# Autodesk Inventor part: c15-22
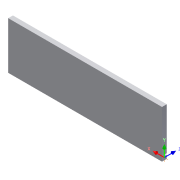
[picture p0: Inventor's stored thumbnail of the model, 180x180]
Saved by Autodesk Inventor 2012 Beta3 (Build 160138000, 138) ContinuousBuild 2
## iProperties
Created: 2011-02
Part Number: c15-22
Material: Default
Document SubType Name: Modeling
Designer: Beta-8540w
Density: 1 g/cm^3
Author: Beta-8540w
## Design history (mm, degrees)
sketch "Sketch1"
  geometry: L1 (-206.375, -63.5)-(206.375, -63.5); L2 (206.375, -63.5)-(206.375, 63.5); L3 (206.375, 63.5)-(-206.375, 63.5); L4 (-206.375, 63.5)-(-206.375, -63.5); 3 further points
  constraints: 8 end point, 2 midpoint, 2 parallel, 1 horizontal, 1 horizontal alignment, 1 perpendicular, 1 vertical alignment
  dimensions: "d0" = 412.75 distance of L3.end L2.end (computed from drawer_depth); "d1" = 127 distance of L2.end L1.end (= drawer_side_height)
extrude "Extrusion1" new body sketch "Sketch1" distance "d2" = 12.7; taper "d3" = 0 deg
sketch "Sketch2"
  geometry: L1 (206.375, -63.5)-(-206.375, -63.5) reference; L2 (206.375, 63.5)-(206.375, -63.5) reference; L3 (-206.375, -63.5)-(-206.375, 63.5) reference; L4 (-206.375, -53.848)-(206.375, -53.848); L5 (206.375, -53.848)-(206.375, -50.546); L6 (206.375, -50.546)-(-206.375, -50.546); L7 (-206.375, -50.546)-(-206.375, -53.848); 1 further point
  constraints: 8 end point, 2 parallel, 2 point on line, 1 horizontal, 1 perpendicular
  dimensions: "d4" = 9.652 distance between parallel lines of L1 L4; "d5" = 3.302 distance of L6.end L4.start (= bottom_thickness)
extrude "Extrusion2" cut sketch "Sketch2" distance "d6" = 6.35; taper "d7" = 0 deg
body "Solid1"
other parameters: "d8" = 6.35, "d9" = 0, "d10" = 0, "d11" = 0, "d12" = 0, "d13" = 0, "drawer_height" = 152.4, "drawer_depth" = 406.4, "drawer_side_height" = 127, "bottom_thickness" = 3.302
